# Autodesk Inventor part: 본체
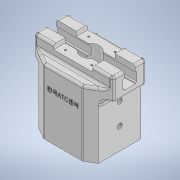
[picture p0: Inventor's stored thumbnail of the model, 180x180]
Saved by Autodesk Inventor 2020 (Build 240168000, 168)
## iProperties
Created: 2023-05
Part Number: 본체
Material: 일반
Document SubType Name: Modeling
Designer: oem
Density: 1 g/cm^3
Appearance: 기본값
Author: oem
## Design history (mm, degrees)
sketch "스케치1"
  geometry: L1 (0, 0)-(126.476, 0); L2 (25.019, -35)-(51, -20); L3 (51, -20)-(51, 20); L4 (25.019, 35)-(51, 20); L5 (0, 0)-(0, -35); L6 (0, -35)-(25.019, -35); L7 (0, 0)-(-126.476, 0); L8 (-25.019, -35)-(-51, -20); L9 (-51, -20)-(-51, 20); L10 (-25.019, 35)-(-51, 20); L11 (0, -35)-(-25.019, -35); L12 (25.019, 35)-(-25.019, 35)
  constraints: 24 end point, 6 symmetric about line, 2 horizontal, 1 vertical
  dimensions: "d7" = 30 deg angle of L1 L2; "d9" = 40 distance of L2.end L3.end; "d10" = 20 distance from line of L1 L2.end; "d11" = 20 distance from line of L1 L3.end; "d33" = 35 distance from line of L1 L2.start; "d34" = 51 distance from line of L1.start L3; "d39" = 35 distance of L1.start L5.end
extrude "돌출1" new body sketch "스케치1" distance "d12" = 29; taper "d13" = 0 deg
sketch "스케치5"
  geometry: L1 (51, 20)-(25.019, 35) reference; L2 (25.019, 35)-(-25.019, 35) reference; L3 (-25.019, 35)-(-51, 20) reference; L4 (-51, -20)-(-25.019, -35) reference; L5 (-25.019, -35)-(25.019, -35) reference; L6 (25.019, -35)-(51, -20) reference; L7 (74.204, -22)-(-74.204, -22); L8 (-74.204, -22)-(-74.204, 22); L9 (-74.204, 22)-(74.204, 22); L10 (74.204, 22)-(74.204, -22); L11 (74.204, -22)-(-74.204, 22); L12 (-74.204, -22)-(74.204, 22); 5 further points
  constraints: 12 end point, 2 midpoint, 2 parallel, 1 horizontal, 1 perpendicular
  dimensions: "d40" = 44 distance of L7.end L8.end; "d41" = 148.40766 distance of L8.end L9.end
extrude "돌출4" cut sketch "스케치5" distance "d42" = 15; taper "d43" = 0 deg
sketch "스케치6"
  geometry: L1 (0, 29)-(40, 29) reference; L2 (20, 29)-(12.8, 29); L3 (12.8, 29)-(12.8, 21.482); L4 (20, 21)-(11, 21); L5 (11, 21)-(11, 10); L6 (11, 21)-(12.8, 21.482); L7 (11, 21)-(14.021, 21); L8 (20, 8)-(12.8, 8); L9 (11, 15.5)-(18.681, 15.5); L10 (11, 10)-(12.8, 9.518); L11 (12.8, 8)-(12.8, 9.518); L12 (20, 8)-(20, 29); L13 (20, 29)-(27.2, 29); L14 (27.2, 29)-(27.2, 21.482); L15 (29, 21)-(29, 10); L16 (29, 10)-(27.2, 9.518); L17 (20, 8)-(27.2, 8); L18 (29, 21)-(27.2, 21.482); L19 (27.2, 8)-(27.2, 9.518); 1 further point
  constraints: 36 end point, 7 symmetric about line, 4 horizontal, 2 midpoint, 2 vertical, 1 perpendicular, 1 point on line
  dimensions: "d44" = 7.2 distance of L2.start L2.end; "d48" = 8 distance from line of L1 L4.end; "d49" = 11 distance of L4.end L5.end; "d50" = 9 horizontal distance of L4.end L2.start; "d51" = 15 deg angle of L7 L6; "d52" = 7.2 distance of L8.start L8.end; "d53" = 21 distance between parallel lines of L8 L1
extrude "돌출5" cut sketch "스케치6" extent not by distance; stored distance "d54" = 0; taper "d55" = 0 deg
sketch "스케치7"
  geometry: L1 (47.536, 22)-(-47.536, 22) reference; L2 (-25, -22)-(25, -22); L3 (25, -22)-(25, 22); L4 (25, 22)-(-25, 22); L5 (-25, 22)-(-25, -22); L6 (-25, -22)-(25, 22); L7 (25, -22)-(-25, 22); 2 further points
  constraints: 12 end point, 2 midpoint, 2 parallel, 1 horizontal, 1 perpendicular, 1 point on line
  dimensions: "d56" = 50 distance of L4.end L3.end
extrude "돌출6" cut sketch "스케치7" distance "d57" = 6; taper "d58" = 0 deg
sketch "스케치15"
  geometry: L1 (0, 0)-(29, 0); L2 (10.392, -6)-(29, -6); L3 (10.392, 6)-(29, 6); L4 (0, 0)-(0, -29.09); L5 (-10.392, -6)-(-29, -6); L6 (-10.392, 6)-(-29, 6); A1 r 6 centre (29, 0) between (29, -6) and (29, 6); A2 r 6 centre (-29, 0) between (-29, 6) and (-29, -6); A3 r 12 centre (0, 0) between (10.392, 6) and (-10.392, 6); A4 r 12 centre (0, 0) between (-10.392, -6) and (10.392, -6); 1 further point
  constraints: 12 end point, 8 point on circle, 5 symmetric about line, 4 centre point, 2 coincident, 2 parallel, 1 horizontal, 1 vertical, 1 other
  dimensions: "d116" = 29 distance of L1.start L1.end; "d117" = 6 distance between parallel lines of L1 L2; "d118" = 6 distance between parallel lines of L1 L3; "d120" = 6 radius of A1; "d121" = 12 radius of A4; "d122" = 12 radius of A3
extrude "돌출8" cut sketch "스케치15" distance "d114" = 30; taper "d115" = 0 deg
sketch "스케치18"
  geometry: L1 (51, -20)-(25.019, -35) reference; L2 (-25.019, -35)-(-51, -20) reference; L3 (25.019, -35)-(-25.019, -35) reference; L4 (0, 0)-(40, 0); L5 (40, 0)-(40, -26.351); L6 (25.019, -35)-(47.536, -22) reference; L7 (40, -26.351)-(25.019, -35); L8 (0, -35)-(0, 0); L9 (0, -35)-(25.019, -35); L10 (-25.019, -35)-(-38.01, -27.5); L11 (-25.019, -35)-(0, -35); L12 (-25.019, 35)-(0, 35); L13 (-25.019, 35)-(-38.01, 27.5); L14 (0, 35)-(25.019, 35); L15 (40, 26.351)-(25.019, 35); L16 (40, 0)-(40, 26.351); L17 (-51, 20)-(-25.019, 35) reference; L18 (0, 0)-(-40, 0); L19 (-40, 0)-(-40, 26.351); L20 (-38.01, 27.5)-(-40, 26.351); L21 (-40, 0)-(-40, -26.351); L22 (-38.01, -27.5)-(-40, -26.351); A1 r 12 centre (0, 0) between (-10.392, -6) and (10.392, -6) reference; A2 r 12 centre (0, 0) between (10.392, 6) and (-10.392, 6) reference
  constraints: 34 end point, 5 collinear, 3 point on line, 3 symmetric about line, 2 horizontal, 2 midpoint, 2 perpendicular, 2 vertical
  dimensions: "d136" = 40 distance of L4.start L4.end; "d254" = 40 distance of L18.start L18.end
extrude "돌출9" join sketch "스케치18" distance "d138" = 70; taper "d139" = 0 deg
node "작업 평면2"
sketch "스케치26"
  geometry: C1 r 10 at (0, 0); 1 further point
  constraints: 1 centre point, 1 coincident
  dimensions: "d180" = 20 diameter of C1
extrude "돌출10" cut sketch "스케치26" stored distance "d181" = 3.2; taper "d182" = 0 deg
sketch "스케치27"
  geometry: A1 r 12 centre (0, 0) between (9.6, 7.2) and (-9.6, 7.2) reference; 1 further point
  dimensions: "d184" = 17 horizontal distance of A1.centre point (-17, 15); "d185" = 15 vertical distance of A1.centre point (-17, 15)
hole "구멍11" sketch "스케치27" at (-17, 15) diameter "d186" = 2.459; stored, may be unused: countersink angle "d190" = 82 deg, drill point angle "d192" = 118 deg; dims "d187" = 6, "d188" = 3.023, "d189" = 2, "d191" = 8
fillet "모깎기2" dims "d232" = 3
fillet "모깎기3" dims "d233" = 3
fillet "모깎기4" dims "d234" = 3
sketch "스케치31"
  geometry: L1 (25.715, -34.598)-(40, -26.351) reference; L2 (40, -26.351)-(40, 26.351) reference; L3 (40, 26.351)-(25.715, 34.598) reference; L4 (38, 31.43)-(38, -34.903); 2 further points
  constraints: 2 end point, 1 vertical
  dimensions: "d235" = 2 distance between parallel lines of L2 L4
extrude "돌출11" cut sketch "스케치31" distance "d236" = 64; taper "d237" = 0 deg
fillet "모깎기5" dims "d248" = 3
sketch "스케치34"
  geometry: 2 further points
  constraints: 1 coincident
hole "구멍16" sketch "스케치34" at (0, 0) diameter "d255" = 60; stored, may be unused: countersink angle "d259" = 90 deg, drill point angle "d261" = 0 deg; dims "d256" = 9, "d257" = 17.3, "d258" = 2, "d260" = 5.8
sketch "스케치35"
  geometry: C1 r 30 at (0, 0) reference; 2 further points
  constraints: 1 coincident
hole "구멍17" sketch "스케치35" at (0, 0) diameter "d262" = 63; stored, may be unused: countersink angle "d266" = 90 deg, drill point angle "d268" = 0 deg; dims "d263" = 9, "d264" = 17.3, "d265" = 2, "d267" = 2.2
sketch "스케치36"
  geometry: C1 r 30 at (0, 0) reference; 2 further points
  constraints: 1 coincident
hole "구멍18" sketch "스케치36" at (0, 0) diameter "d269" = 60; stored, may be unused: countersink angle "d273" = 90 deg, drill point angle "d275" = 0 deg; dims "d270" = 9, "d271" = 17.3, "d272" = 2, "d274" = 6
sketch "스케치37"
  geometry: C1 r 30 at (0, 0) reference; 2 further points
  constraints: 1 coincident
hole "구멍19" sketch "스케치37" at (0, 0) diameter "d276" = 50; stored, may be unused: countersink angle "d280" = 90 deg, drill point angle "d282" = 0 deg; dims "d277" = 9, "d278" = 17.3, "d279" = 2, "d281" = 45
chamfer "모따기4" distance "d283" = 2; stored, may be unused: second distance "d284" = 2, angle "d285" = 20 deg
sketch "스케치39"
  geometry: C1 r 25 at (0, 0) reference; 2 further points
  constraints: 1 coincident
hole "구멍20" sketch "스케치39" at (0, 0) diameter "d286" = 16; stored, may be unused: countersink angle "d290" = 90 deg, drill point angle "d292" = 0 deg; dims "d287" = 9, "d288" = 17.3, "d289" = 2, "d291" = 45
sketch "스케치40"
  geometry: L1 (55.011, 0)-(0, 0) reference; L2 (-7.494, 81)-(-7.494, 0) reference; 2 further points
  dimensions: "d293" = 28 distance from line of L1 point (27.506, 28); "d294" = 35 distance from line of point (27.506, 28) L2
hole "구멍21" sketch "스케치40" at (27.506, 28) diameter "d295" = 4; stored, may be unused: countersink angle "d299" = 90 deg, drill point angle "d301" = 0 deg; dims "d296" = 9, "d297" = 17.3, "d298" = 2, "d300" = 45
sketch "스케치41"
  geometry: C1 r 2 at (27.506, 28) reference; 2 further points
  constraints: 1 coincident
hole "구멍22" sketch "스케치41" at (27.506, 28) diameter "d302" = 6.647; stored, may be unused: countersink angle "d306" = 90 deg, drill point angle "d308" = 118 deg; dims "d303" = 9, "d304" = 17.3, "d305" = 2, "d307" = 11
sketch "스케치42"
  geometry: L1 (-15.785, 73)-(-15.785, 0) reference; L2 (70.947, 99)-(49.215, 99) reference; 2 further points
  constraints: 1 other
  dimensions: "d312" = 40 distance from line of L1 point (24.215, 59); "d313" = 40 distance from line of point (24.215, 59) L2
feature "엠보싱1" sketch "스케치42" dims "d314" = 0.5, "d315" = 0
node "솔리드1"
pattern_linear "직사각형 패턴1" dims "d195" = 34, "d198" = 30
pattern_linear "직사각형 패턴4" dims "d311" = 28
feature "A9D066F2-1C7D-4E18-AEED-F7BC21143FA4" dims "d186" = 2.459, "d187" = 6, "d188" = 3.023, "d189" = 2, "d190" = 82 deg, "d191" = 8, "d192" = 118 deg
other parameters: "d179" = -5
